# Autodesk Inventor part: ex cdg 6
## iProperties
Shininess: 20.0
Angle Display Precision: 2
Document Length Units: 11269
Document Angle Units: 11279
Document Time Units: 11290
Document Mass Units: 11283
Document Length Units Precision: 3
Document Angle Units Precision: 2
Created: 2002-05
Part Number: ex cdg 6
Material: Laiton (jaune doux)
Document SubType Name: Modélisation
Designer: Administrateur
Density: 0.0
Volumn: 0.0
Area: 0.0
PropertySet Name: Model Information
Control State: 0
Master: False
Checked Out: False
Author: Administrateur
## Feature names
1. Extrusion1
2. Extrusion2
3. Extrusion3
4. Extrusion4
5. Extrusion5
6. Perçage1 [Hole]
